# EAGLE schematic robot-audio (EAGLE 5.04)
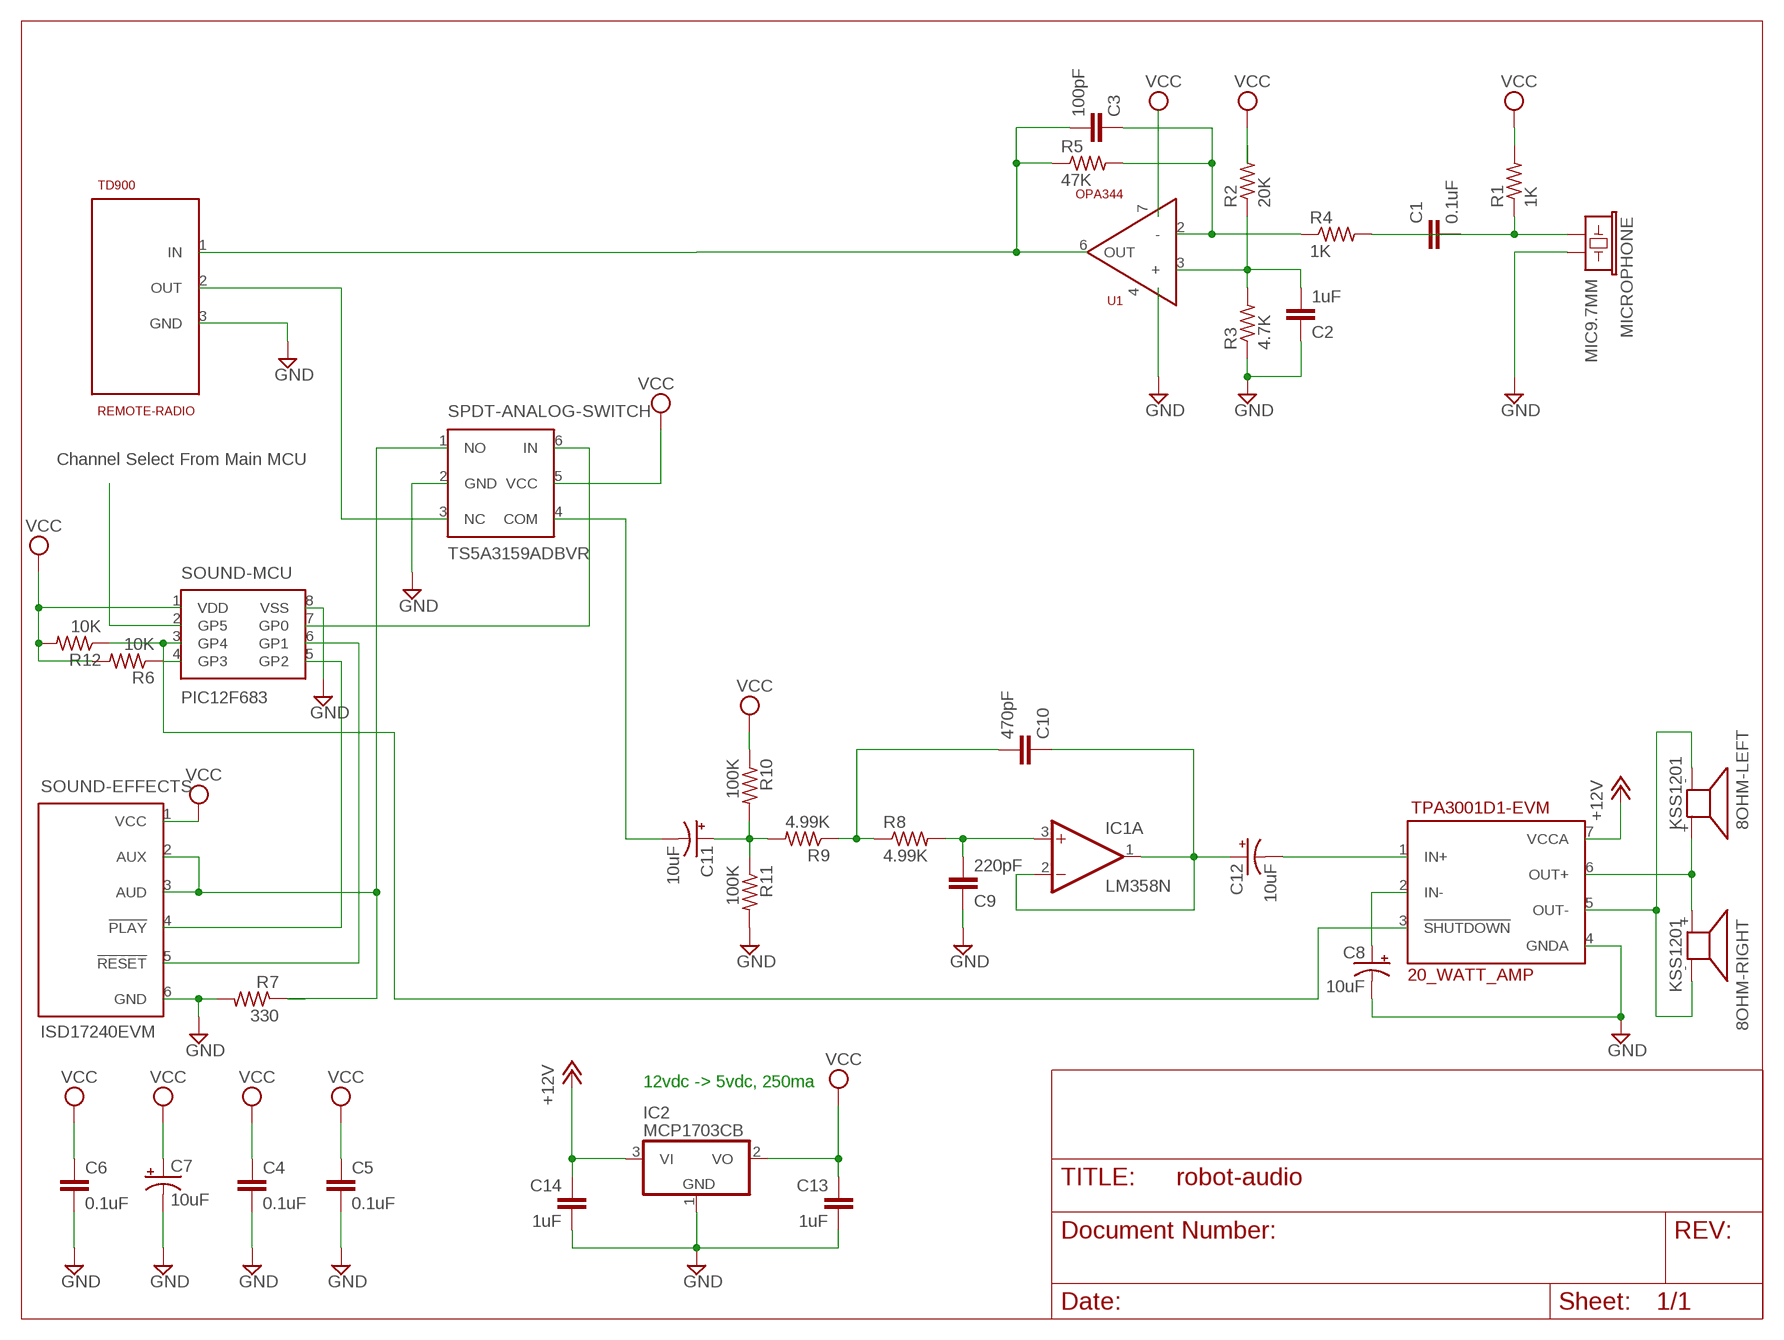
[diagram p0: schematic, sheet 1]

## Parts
8OHM-LEFT  KSS1201  [KSS1201]
8OHM-RIGHT  KSS1201  [KSS1201]
20_WATT_AMP  TPA3001D1-EVM  [7SIL]
C1  0.1uF  C5/3.5  [C5B3.5]
C2  1uF  C5/3.5  [C5B3.5]
C3  100pF  C5/3.5  [C5B3.5]
C4  0.1uF  C5/3.5  [C5B3.5]
C5  0.1uF  C5/3.5  [C5B3.5]
C6  0.1uF  C5/3.5  [C5B3.5]
C7  10uF  CPOL-USB45181D  [B45181D]
C8  10uF  CPOL-USB45181D  [B45181D]
C9  220pF  C5/3.5  [C5B3.5]
C10  470pF  C5/3.5  [C5B3.5]
C11  10uF  CPOL-USB45181D  [B45181D]
C12  10uF  CPOL-USB45181D  [B45181D]
C13  1uF  C5/3.5  [C5B3.5]
C14  1uF  C5/3.5  [C5B3.5]
IC1  LM358N  [DIL08]
IC2  MCP1703CB  [SOT23]
MICROPHONE  MIC9.7MM  [MIC-9.7MM]
R1  1K  R-US_0817/22  [P0817/22]
R2  20K  R-US_0817/22  [P0817/22]
R3  4.7K  R-US_0817/22  [P0817/22]
R4  1K  R-US_0817/22  [P0817/22]
R5  47K  R-US_0817/22  [P0817/22]
R6  10K  R-US_0817/22  [P0817/22]
R7  330  R-US_0817/22  [P0817/22]
R8  4.99K  R-US_0817/22  [P0817/22]
R9  4.99K  R-US_0817/22  [P0817/22]
R10  100K  R-US_0817/22  [P0817/22]
R11  100K  R-US_0817/22  [P0817/22]
R12  10K  R-US_0817/22  [P0817/22]
REMOTE-RADIO  TD900  [3SIL]
SOUND-EFFECTS  ISD17240EVM  [6SIL]
SOUND-MCU  PIC12F683  [8DIP]
SPDT-ANALOG-SWITCH  TS5A3159ADBVR  [SOT23-6]
U1  OPA344  [8DIP]

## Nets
+12V: 20_WATT_AMP.7(VCCA) C14.1 IC2.3(VI)
GND: 20_WATT_AMP.4(GNDA) C2.1 C4.2 C5.2 C6.2 C7.- C8.- C9.1 C13.2 C14.2 IC2.1(GND) MICROPHONE.2 R3.1 R7.2 R11.2 REMOTE-RADIO.3(GND) SOUND-EFFECTS.6(GND) SOUND-MCU.8(VSS) SPDT-ANALOG-SWITCH.2(GND)
N$2: 8OHM-LEFT.+ 8OHM-RIGHT.+ 20_WATT_AMP.6(OUT+)
N$3: C3.2 R5.1 REMOTE-RADIO.1(IN) U1.6(OUT)
N$4: 20_WATT_AMP.2(IN-) C8.+
N$5: C1.2 MICROPHONE.1 R1.1 R4.2
N$6: C2.2 R2.1 R3.2 U1.3(+)
N$8: C3.1 R4.1 R5.2 U1.2(-)
N$9: REMOTE-RADIO.2(OUT) SPDT-ANALOG-SWITCH.3(NC)
N$10: SOUND-EFFECTS.4(!PLAY) SOUND-MCU.5(GP2)
N$11: SOUND-MCU.7(GP0) SPDT-ANALOG-SWITCH.6(IN)
N$12: R6.1 SOUND-MCU.4(GP3)
N$13: SOUND-EFFECTS.5(!RESET) SOUND-MCU.6(GP1)
N$14: 20_WATT_AMP.1(IN+) C12.-
N$15: C11.- SPDT-ANALOG-SWITCH.4(COM)
N$17: C10.1 C12.+ IC1.1(A:OUT) IC1.2(A:-IN)
N$18: R7.1 SOUND-EFFECTS.2(AUX) SOUND-EFFECTS.3(AUD) SPDT-ANALOG-SWITCH.1(NO)
N$19: C9.2 IC1.3(A:+IN) R8.2
N$20: C10.2 R8.1 R9.1
N$21: C11.+ R9.2 R10.2 R11.1
N$22: 20_WATT_AMP.3(!SHUTDOWN) R12.1 SOUND-MCU.3(GP4)
N$23: 8OHM-LEFT.- 8OHM-RIGHT.- 20_WATT_AMP.5(OUT-)
N$24: SOUND-MCU.2(GP5)
VCC: C4.1 C5.1 C6.1 C7.+ C13.1 IC2.2(VO) R1.2 R6.2 R10.1 R12.2 SOUND-EFFECTS.1(VCC) SOUND-MCU.1(VDD) SPDT-ANALOG-SWITCH.5(VCC)
Unconnected: C1.1 IC1.5(B:+IN) IC1.6(B:-IN) IC1.7(B:OUT) R2.2 U1.4(GND) U1.7(VCC)

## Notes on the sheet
- Channel Select From Main MCU
- 12vdc -> 5vdc, 250ma

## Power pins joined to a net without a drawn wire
V+: IC1.8(P:V+)
V-: IC1.4(P:V-)

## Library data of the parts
8OHM-LEFT 8OHM-RIGHT = buzzer:KSS1201: SPEAKER
20_WATT_AMP = trl:TPA3001D1-EVM
C1-C6 C9 C10 C13 C14 = capacitor-wima:C: CAPACITOR
C7 C8 C11 C12 = resistor:CPOL-US: POLARIZED CAPACITOR, American symbol
IC1 = linear:LM358: OP AMP also LM158; LM258; LM2904 Source: http://cache.national.com/ds/LM/LM158.pdf
IC2 = linear:MCP1703: 250 mA, 16V, Low Quiescent Current LDO Regulator Source: http://ww1.microchip.com/downloads/en/DeviceDoc/22049b.pdf
MICROPHONE = SparkFun:MIC: Microphone
R1-R12 = rcl:R-US_: RESISTOR, American symbol
REMOTE-RADIO = trl:TD900
SOUND-EFFECTS = trl:ISD17240EVM: 240 Second Pre-Recorded Sound Effects Player
SOUND-MCU = trl:PIC12F683
SPDT-ANALOG-SWITCH = trl:TS5A3159ADBVR: SPDT Analog Switch
U1 = trl:OPA344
